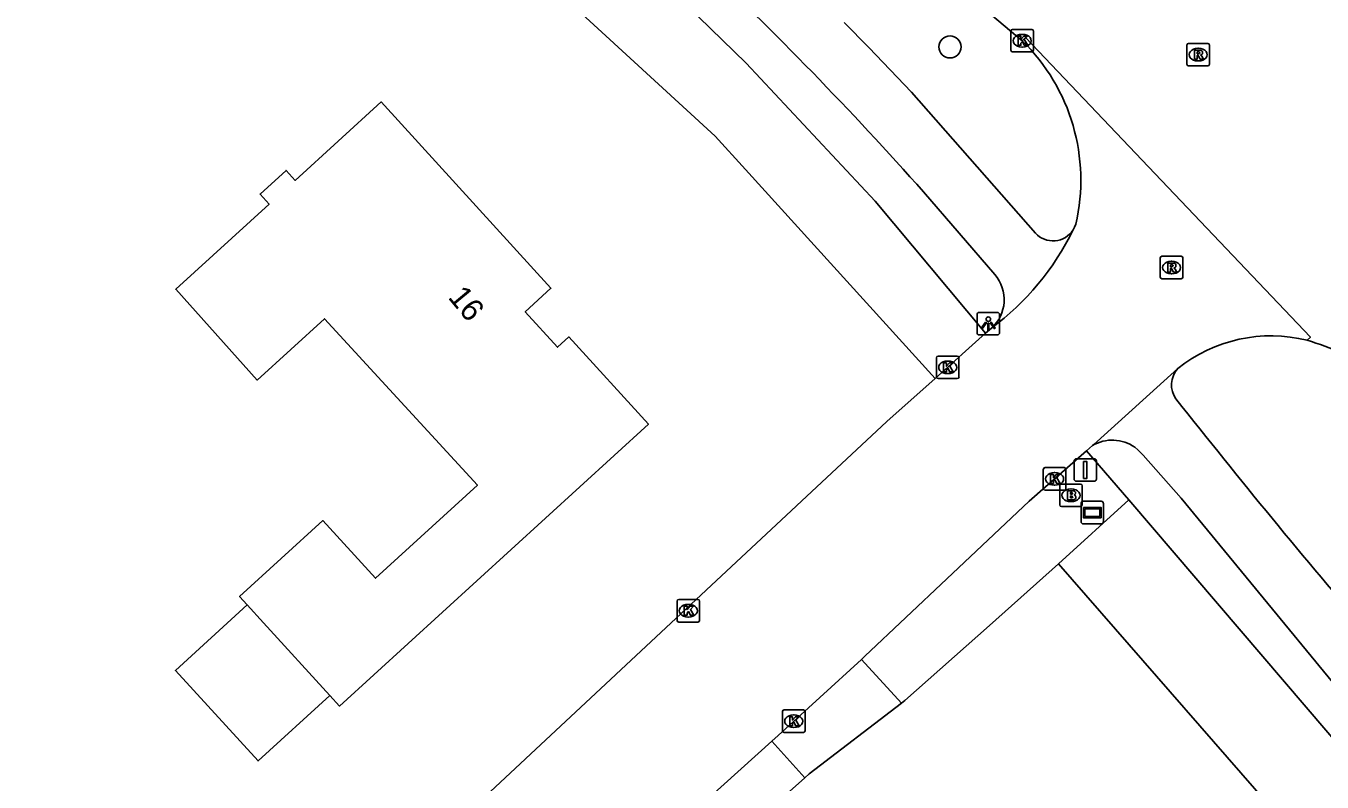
# Model space of a CAD drawing. Extents: x 162417 to 163721, y 384268 to 385416.
# Drawn here: x 163382.6 to 163440.1, y 385193.2 to 385226.8 of the extents above; entities that cross this region are included whole.
import ezdxf

# ---------------------------------------------------------------- set-up
doc = ezdxf.new("R2010")
doc.units = 0
for name, color, linetype in [('IMGEO_Boom', 7, 'Continuous'), ('IMGEO_Brandkraan', 7, 'Continuous'), ('IMGEO_Fietspad_open', 7, 'Continuous'), ('IMGEO_Gemengd_bos', 7, 'Continuous'), ('IMGEO_Groenvoorziening', 7, 'Continuous'), ('IMGEO_Kolk', 7, 'Continuous'), ('IMGEO_Lichtpunt', 7, 'Continuous'), ('IMGEO_Pand', 7, 'Continuous'), ('IMGEO_Pand_nummerreeks', 7, 'Continuous'), ('IMGEO_Rijbaan_lokaal_gesloten', 7, 'Continuous'), ('IMGEO_Rioolput', 7, 'Continuous'), ('IMGEO_Verkeersbordpaal', 7, 'Continuous'), ('IMGEO_Verklikker', 7, 'Continuous'), ('IMGEO_Voetpad_open', 7, 'Continuous')]:
    doc.layers.add(name, color=color, linetype=linetype)

msp = doc.modelspace()

# ---------------------------------------------------------------- linework, layer by layer
at = {"layer": 'IMGEO_Boom'}
msp.add_circle((163423.593, 385225.822), 0.489, dxfattribs=at)
at = {"layer": 'IMGEO_Brandkraan'}
for p, q in [((163428.459, 385205.514), (163428.459, 385206.366)), ((163428.534, 385206.44), (163429.386, 385206.44)), ((163428.947, 385206.22), (163428.972, 385206.22)), ((163429.46, 385206.366), (163429.46, 385205.514)), ((163429.386, 385205.44), (163428.534, 385205.44)), ((163428.97, 385205.66), (163428.945, 385205.66))]:
    msp.add_line(p, q, dxfattribs=at)
for points in [[(163428.459, 385205.514), (163428.459, 385206.366)], [(163428.534, 385206.44), (163429.386, 385206.44)], [(163428.807, 385206.14), (163428.807, 385205.74), (163429.02, 385205.74)], [(163429.038, 385206.14), (163428.807, 385206.14)], [(163428.986, 385206.059), (163428.932, 385206.059), (163428.932, 385205.983)], [(163428.932, 385205.983), (163428.985, 385205.983)], [(163429.46, 385206.366), (163429.46, 385205.514)], [(163429.386, 385205.44), (163428.534, 385205.44)], [(163428.994, 385205.907), (163428.932, 385205.907), (163428.932, 385205.826)], [(163428.932, 385205.826), (163428.994, 385205.826)]]:
    msp.add_lwpolyline(points, dxfattribs=at)
for centre, radius, start, end in [((163428.536, 385206.364), 0.0765, 91.55205, 178.44795), ((163428.536, 385206.364), 0.0765, 91.55205, 178.44795), ((163428.987, 385206.021), 0.0379, 267.82845, 90.93552), ((163429.042, 385205.995), 0.145, 59.4692, 91.53667), ((163429.067, 385206.042), 0.0922, 285.51372, 58.15012), ((163429.072, 385205.85), 0.105, 301.31148, 78.98903), ((163429.384, 385206.364), 0.0765, 1.55205, 88.44795), ((163429.384, 385206.364), 0.0765, 1.55205, 88.44795), ((163428.536, 385205.516), 0.0765, 181.55205, 268.44795), ((163428.536, 385205.516), 0.0765, 181.55205, 268.44795), ((163428.995, 385205.866), 0.0404, 269.87594, 90.50774), ((163429.026, 385205.991), 0.251, 268.66757, 293.53466), ((163429.384, 385205.516), 0.0765, 271.55205, 358.44795), ((163429.384, 385205.516), 0.0765, 271.55205, 358.44795)]:
    msp.add_arc(centre, radius, start, end, dxfattribs=at)
for centre, major_axis, ratio, start_param, end_param in [((163428.946, 385205.94), (-0.387, 0.002), 0.722429, 4.712389, 7.853982), ((163428.971, 385205.94), (-0.39, 0.002), 0.717154, 1.570796, 4.712389)]:
    msp.add_ellipse(centre, major_axis=major_axis, ratio=ratio, start_param=start_param, end_param=end_param, dxfattribs=at)
at = {"layer": 'IMGEO_Fietspad_open'}
for points in [[(163427.379, 385217.563), (163421.89, 385223.809), (163419.988, 385225.795), (163418.903, 385226.906)], [(163422.42, 385219.391), (163425.582, 385215.726)], [(163431.787, 385208.07), (163431.922, 385207.954), (163432.159, 385207.714), (163433.841, 385205.808), (163444.2, 385193.223), (163470.237, 385163.265), (163478.767, 385152.569), (163484.279, 385144.583), (163488.178, 385138.38), (163494.183, 385128.236), (163502.766, 385111.711), (163507.809, 385101.794), (163517.384, 385082.877), (163528.502, 385060.963)]]:
    msp.add_lwpolyline(points, dxfattribs=at)
for centre, radius, start, end in [((163299.088, 385109.656), 165.084, 41.6612, 46.68774), ((163428.16, 385218.28), 1.06, 222.5679, 327.40112), ((163424.297, 385214.615), 1.698, 311.7937, 40.84056), ((163434.498, 385210.835), 1.084, 137.77915, 214.9254), ((163733.724, 385447.945), 382.864, 218.38399, 220.41896), ((163430.791, 385206.657), 1.729, 54.82845, 120.65616)]:
    msp.add_arc(centre, radius, start, end, dxfattribs=at)
at = {"layer": 'IMGEO_Gemengd_bos'}
for points in [[(163431.516, 385205.744), (163428.403, 385202.907)], [(163309.738, 385096.794), (163334.35, 385105.91), (163401.172, 385130.32), (163403.611, 385131.145), (163408.387, 385133.189), (163412.924, 385135.721), (163417.172, 385138.714), (163421.083, 385142.134), (163454.583, 385172.899), (163428.403, 385202.907)]]:
    msp.add_lwpolyline(points, dxfattribs=at)
at = {"layer": 'IMGEO_Groenvoorziening'}
for points in [[(163397.756, 385235.453), (163401.687, 385232.409), (163413.183, 385221.864), (163414.526, 385220.382), (163422.928, 385211.112)], [(163428.403, 385202.907), (163425.337, 385200.174), (163421.592, 385196.836), (163421.439, 385196.719)], [(163417.147, 385193.417), (163401.29, 385179.305), (163399.075, 385177.547)]]:
    msp.add_lwpolyline(points, dxfattribs=at)
at = {"layer": 'IMGEO_Kolk'}
for p, q in [((163426.293, 385225.67), (163426.293, 385226.522)), ((163426.368, 385226.596), (163427.22, 385226.596)), ((163426.781, 385226.376), (163426.806, 385226.376)), ((163427.294, 385226.522), (163427.294, 385225.67)), ((163427.22, 385225.596), (163426.368, 385225.596)), ((163426.804, 385225.816), (163426.779, 385225.816)), ((163422.99, 385211.187), (163422.99, 385212.039)), ((163423.065, 385212.113), (163423.917, 385212.113)), ((163423.478, 385211.893), (163423.503, 385211.893)), ((163423.991, 385212.039), (163423.991, 385211.187)), ((163423.917, 385211.113), (163423.065, 385211.113)), ((163423.501, 385211.333), (163423.476, 385211.333)), ((163427.731, 385206.241), (163427.731, 385207.093)), ((163427.806, 385207.167), (163428.658, 385207.167)), ((163428.732, 385207.093), (163428.732, 385206.241)), ((163428.219, 385206.947), (163428.244, 385206.947)), ((163428.658, 385206.167), (163427.806, 385206.167)), ((163428.242, 385206.387), (163428.217, 385206.387)), ((163411.485, 385200.395), (163411.485, 385201.247)), ((163411.56, 385201.321), (163412.412, 385201.321)), ((163411.973, 385201.101), (163411.998, 385201.101)), ((163412.486, 385201.247), (163412.486, 385200.395)), ((163412.412, 385200.321), (163411.56, 385200.321)), ((163411.996, 385200.541), (163411.971, 385200.541)), ((163416.161, 385195.497), (163416.161, 385196.349)), ((163416.236, 385196.423), (163417.088, 385196.423)), ((163416.649, 385196.203), (163416.674, 385196.203)), ((163417.162, 385196.349), (163417.162, 385195.497)), ((163416.672, 385195.643), (163416.647, 385195.643)), ((163417.088, 385195.423), (163416.236, 385195.423))]:
    msp.add_line(p, q, dxfattribs=at)
for points in [[(163426.293, 385225.67), (163426.293, 385226.522)], [(163426.368, 385226.596), (163427.22, 385226.596)], [(163426.614, 385226.296), (163426.737, 385226.296), (163426.737, 385226.145), (163426.867, 385226.296), (163427.031, 385226.296), (163426.885, 385226.145), (163427.038, 385225.896), (163426.886, 385225.896), (163426.801, 385226.06), (163426.737, 385225.993), (163426.737, 385225.896), (163426.614, 385225.896), (163426.614, 385226.296)], [(163427.294, 385226.522), (163427.294, 385225.67)], [(163427.22, 385225.596), (163426.368, 385225.596)], [(163422.99, 385211.187), (163422.99, 385212.039)], [(163423.065, 385212.113), (163423.917, 385212.113)], [(163423.311, 385211.813), (163423.434, 385211.813), (163423.434, 385211.662), (163423.564, 385211.813), (163423.728, 385211.813), (163423.582, 385211.662), (163423.735, 385211.413), (163423.583, 385211.413), (163423.498, 385211.577), (163423.434, 385211.51), (163423.434, 385211.413), (163423.311, 385211.413), (163423.311, 385211.813)], [(163423.991, 385212.039), (163423.991, 385211.187)], [(163423.917, 385211.113), (163423.065, 385211.113)], [(163427.731, 385206.241), (163427.731, 385207.093)], [(163427.806, 385207.167), (163428.658, 385207.167)], [(163428.732, 385207.093), (163428.732, 385206.241)], [(163428.052, 385206.867), (163428.175, 385206.867), (163428.175, 385206.716), (163428.305, 385206.867), (163428.469, 385206.867), (163428.323, 385206.716), (163428.476, 385206.467), (163428.324, 385206.467), (163428.239, 385206.631), (163428.175, 385206.564), (163428.175, 385206.467), (163428.052, 385206.467), (163428.052, 385206.867)], [(163428.658, 385206.167), (163427.806, 385206.167)], [(163411.485, 385200.395), (163411.485, 385201.247)], [(163411.56, 385201.321), (163412.412, 385201.321)], [(163411.806, 385201.021), (163411.929, 385201.021), (163411.929, 385200.87), (163412.059, 385201.021), (163412.223, 385201.021), (163412.077, 385200.87), (163412.23, 385200.621), (163412.078, 385200.621), (163411.993, 385200.785), (163411.929, 385200.718), (163411.929, 385200.621), (163411.806, 385200.621), (163411.806, 385201.021)], [(163412.486, 385201.247), (163412.486, 385200.395)], [(163412.412, 385200.321), (163411.56, 385200.321)], [(163416.161, 385195.497), (163416.161, 385196.349)], [(163416.236, 385196.423), (163417.088, 385196.423)], [(163417.162, 385196.349), (163417.162, 385195.497)], [(163416.482, 385196.123), (163416.605, 385196.123), (163416.605, 385195.972), (163416.735, 385196.123), (163416.899, 385196.123), (163416.753, 385195.972), (163416.906, 385195.723), (163416.754, 385195.723), (163416.669, 385195.887), (163416.605, 385195.82), (163416.605, 385195.723), (163416.482, 385195.723), (163416.482, 385196.123)], [(163417.088, 385195.423), (163416.236, 385195.423)]]:
    msp.add_lwpolyline(points, dxfattribs=at)
for centre, start, end in [((163426.37, 385226.52), 91.55205, 178.44795), ((163426.37, 385226.52), 91.55205, 178.44795), ((163427.218, 385226.52), 1.55205, 88.44795), ((163427.218, 385226.52), 1.55205, 88.44795), ((163426.37, 385225.672), 181.55205, 268.44795), ((163426.37, 385225.672), 181.55205, 268.44795), ((163427.218, 385225.672), 271.55205, 358.44795), ((163427.218, 385225.672), 271.55205, 358.44795), ((163423.067, 385212.037), 91.55205, 178.44795), ((163423.067, 385212.037), 91.55205, 178.44795), ((163423.915, 385212.037), 1.55205, 88.44795), ((163423.915, 385212.037), 1.55205, 88.44795), ((163423.067, 385211.189), 181.55205, 268.44795), ((163423.067, 385211.189), 181.55205, 268.44795), ((163423.915, 385211.189), 271.55205, 358.44795), ((163423.915, 385211.189), 271.55205, 358.44795), ((163427.808, 385207.091), 91.55205, 178.44795), ((163427.808, 385207.091), 91.55205, 178.44795), ((163428.656, 385207.091), 1.55205, 88.44795), ((163428.656, 385207.091), 1.55205, 88.44795), ((163427.808, 385206.243), 181.55205, 268.44795), ((163427.808, 385206.243), 181.55205, 268.44795), ((163428.656, 385206.243), 271.55205, 358.44795), ((163428.656, 385206.243), 271.55205, 358.44795), ((163411.562, 385201.245), 91.55205, 178.44795), ((163411.562, 385201.245), 91.55205, 178.44795), ((163412.41, 385201.245), 1.55205, 88.44795), ((163412.41, 385201.245), 1.55205, 88.44795), ((163411.562, 385200.397), 181.55205, 268.44795), ((163411.562, 385200.397), 181.55205, 268.44795), ((163412.41, 385200.397), 271.55205, 358.44795), ((163412.41, 385200.397), 271.55205, 358.44795), ((163416.238, 385196.347), 91.55205, 178.44795), ((163416.238, 385196.347), 91.55205, 178.44795), ((163417.086, 385196.347), 1.55205, 88.44795), ((163417.086, 385196.347), 1.55205, 88.44795), ((163416.238, 385195.499), 181.55205, 268.44795), ((163416.238, 385195.499), 181.55205, 268.44795), ((163417.086, 385195.499), 271.55205, 358.44795), ((163417.086, 385195.499), 271.55205, 358.44795)]:
    msp.add_arc(centre, 0.0765, start, end, dxfattribs=at)
for centre, major_axis, ratio, start_param, end_param in [((163426.78, 385226.096), (-0.387, 0.002), 0.722429, 4.712389, 7.853982), ((163426.805, 385226.096), (-0.39, 0.002), 0.717154, 1.570796, 4.712389), ((163423.477, 385211.613), (-0.387, 0.002), 0.722429, 4.712389, 7.853982), ((163423.502, 385211.613), (-0.39, 0.002), 0.717154, 1.570796, 4.712389), ((163428.218, 385206.667), (-0.387, 0.002), 0.722429, 4.712389, 7.853982), ((163428.243, 385206.667), (-0.39, 0.002), 0.717154, 1.570796, 4.712389), ((163411.972, 385200.821), (-0.387, 0.002), 0.722429, 4.712389, 7.853982), ((163411.997, 385200.821), (-0.39, 0.002), 0.717154, 1.570796, 4.712389), ((163416.648, 385195.923), (-0.387, 0.002), 0.722429, 4.712389, 7.853982), ((163416.673, 385195.923), (-0.39, 0.002), 0.717154, 1.570796, 4.712389)]:
    msp.add_ellipse(centre, major_axis=major_axis, ratio=ratio, start_param=start_param, end_param=end_param, dxfattribs=at)
at = {"layer": 'IMGEO_Lichtpunt'}
for p, q in [((163425.693, 385214.049), (163424.885, 385214.049)), ((163425.693, 385214.049), (163424.885, 385214.049)), ((163424.791, 385213.954), (163424.791, 385213.147)), ((163424.791, 385213.954), (163424.791, 385213.147)), ((163425.787, 385213.147), (163425.787, 385213.954)), ((163425.787, 385213.147), (163425.787, 385213.954)), ((163424.885, 385213.053), (163425.693, 385213.053)), ((163424.885, 385213.053), (163425.693, 385213.053))]:
    msp.add_line(p, q, dxfattribs=at)
for points in [[(163425.165, 385213.618), (163425.204, 385213.59), (163425.016, 385213.328), (163424.978, 385213.355), (163425.165, 385213.618)], [(163425.267, 385213.57), (163425.314, 385213.57), (163425.314, 385213.248), (163425.267, 385213.248), (163425.267, 385213.57)], [(163425.377, 385213.59), (163425.415, 385213.617), (163425.602, 385213.355), (163425.563, 385213.327), (163425.377, 385213.59)]]:
    msp.add_lwpolyline(points, dxfattribs=at)
msp.add_circle((163425.29, 385213.752), 0.0994, dxfattribs=at)
for centre, start, end in [((163424.885, 385213.954), 90, 180), ((163424.885, 385213.954), 90, 180), ((163425.693, 385213.954), 0, 90), ((163425.693, 385213.954), 0, 90), ((163424.885, 385213.147), 180, 270), ((163424.885, 385213.147), 180, 270), ((163425.693, 385213.147), 270, 0), ((163425.693, 385213.147), 270, 360)]:
    msp.add_arc(centre, 0.0946, start, end, dxfattribs=at)
at = {"layer": 'IMGEO_Pand'}
for points in [[(163396.087, 385197.066), (163396.516, 385196.596), (163410.218, 385209.096), (163406.69, 385212.964), (163406.188, 385212.506), (163404.754, 385214.078), (163405.896, 385215.12), (163398.36, 385223.379), (163394.548, 385219.902), (163394.145, 385220.346), (163392.992, 385219.297), (163393.397, 385218.854), (163389.252, 385215.074), (163392.871, 385211.048), (163395.852, 385213.768), (163402.635, 385206.393), (163398.11, 385202.265), (163395.781, 385204.819), (163392.088, 385201.45), (163392.426, 385201.079)], [(163392.426, 385201.079), (163389.243, 385198.175), (163392.904, 385194.162), (163396.087, 385197.066)], [(163396.087, 385197.066), (163393.147, 385200.29), (163392.426, 385201.079)]]:
    msp.add_lwpolyline(points, dxfattribs=at)
at = {"layer": 'IMGEO_Rijbaan_lokaal_gesloten'}
for points in [[(163423.595, 385228.801), (163426.798, 385226.095)], [(163426.798, 385226.095), (163426.943, 385226.233), (163439.577, 385212.956), (163439.432, 385212.818)], [(163429.053, 385217.709), (163429.117, 385217.832), (163429.17, 385217.958)], [(163422.928, 385211.112), (163425.17, 385213.131)], [(163425.17, 385213.131), (163425.429, 385213.349)], [(163394.726, 385185.434), (163400.757, 385190.511), (163420.795, 385209.205), (163422.928, 385211.112)], [(163433.695, 385211.563), (163430.116, 385208.329), (163429.964, 385208.192), (163429.91, 385208.144)], [(163429.648, 385207.914), (163427.108, 385205.674), (163423.458, 385202.232), (163419.819, 385198.801), (163419.667, 385198.662)], [(163429.91, 385208.144), (163429.648, 385207.914)], [(163419.667, 385198.662), (163415.974, 385195.293), (163415.688, 385195.035)], [(163415.688, 385195.035), (163402.705, 385183.33), (163398.036, 385179.474)]]:
    msp.add_lwpolyline(points, dxfattribs=at)
for centre, radius, start, end in [((163420.738, 385219.914), 8.656, 346.93805, 45.56559), ((163418.291, 385222.968), 11.978, 306.57759, 333.95619), ((163437.843, 385206.341), 6.669, 76.21663, 128.46214), ((163434.996, 385198.578), 14.915, 60.05669, 72.69854)]:
    msp.add_arc(centre, radius, start, end, dxfattribs=at)
at = {"layer": 'IMGEO_Rioolput'}
for p, q in [((163434.099, 385225.053), (163434.099, 385225.905)), ((163434.174, 385225.979), (163435.026, 385225.979)), ((163434.587, 385225.759), (163434.612, 385225.759)), ((163435.1, 385225.905), (163435.1, 385225.053)), ((163435.026, 385224.979), (163434.174, 385224.979)), ((163434.61, 385225.199), (163434.585, 385225.199)), ((163432.917, 385215.613), (163432.917, 385216.465)), ((163432.992, 385216.539), (163433.844, 385216.539)), ((163433.405, 385216.319), (163433.43, 385216.319)), ((163433.918, 385216.465), (163433.918, 385215.613)), ((163433.428, 385215.759), (163433.403, 385215.759)), ((163433.844, 385215.539), (163432.992, 385215.539))]:
    msp.add_line(p, q, dxfattribs=at)
for points in [[(163434.099, 385225.053), (163434.099, 385225.905)], [(163434.174, 385225.979), (163435.026, 385225.979)], [(163434.688, 385225.677), (163434.436, 385225.679), (163434.436, 385225.279)], [(163434.614, 385225.598), (163434.56, 385225.598), (163434.56, 385225.517)], [(163434.56, 385225.517), (163434.612, 385225.517)], [(163435.1, 385225.905), (163435.1, 385225.053)], [(163435.026, 385224.979), (163434.174, 385224.979)], [(163434.436, 385225.279), (163434.56, 385225.279), (163434.56, 385225.441), (163434.571, 385225.441)], [(163434.618, 385225.412), (163434.689, 385225.279), (163434.829, 385225.279), (163434.764, 385225.405)], [(163432.917, 385215.613), (163432.917, 385216.465)], [(163432.992, 385216.539), (163433.844, 385216.539)], [(163433.918, 385216.465), (163433.918, 385215.613)], [(163433.506, 385216.237), (163433.254, 385216.239), (163433.254, 385215.839)], [(163433.254, 385215.839), (163433.378, 385215.839), (163433.378, 385216.001), (163433.389, 385216.001)], [(163433.432, 385216.158), (163433.378, 385216.158), (163433.378, 385216.077)], [(163433.378, 385216.077), (163433.43, 385216.077)], [(163433.436, 385215.972), (163433.507, 385215.839), (163433.647, 385215.839), (163433.582, 385215.965)], [(163433.844, 385215.539), (163432.992, 385215.539)]]:
    msp.add_lwpolyline(points, dxfattribs=at)
for centre, radius, start, end in [((163434.176, 385225.903), 0.0765, 91.55205, 178.44795), ((163434.176, 385225.903), 0.0765, 91.55205, 178.44795), ((163434.596, 385225.706), 0.19, 274.7715, 282.96867), ((163434.62, 385225.502), 0.0964, 77.00612, 93.18647), ((163434.634, 385225.559), 0.0378, 276.66336, 79.67722), ((163434.687, 385225.567), 0.109, 350.36119, 89.41601), ((163434.685, 385225.567), 0.112, 277.58423, 350.98172), ((163435.024, 385225.903), 0.0765, 1.55205, 88.44795), ((163435.024, 385225.903), 0.0765, 1.55205, 88.44795), ((163434.176, 385225.055), 0.0765, 181.55205, 268.44795), ((163434.176, 385225.055), 0.0765, 181.55205, 268.44795), ((163434.57, 385225.388), 0.0533, 26.02933, 88.69889), ((163434.669, 385225.352), 0.108, 29.51342, 73.79051), ((163435.024, 385225.055), 0.0765, 271.55205, 358.44795), ((163435.024, 385225.055), 0.0765, 271.55205, 358.44795), ((163432.994, 385216.463), 0.0765, 91.55205, 178.44795), ((163432.994, 385216.463), 0.0765, 91.55205, 178.44795), ((163433.842, 385216.463), 0.0765, 1.55205, 88.44795), ((163433.842, 385216.463), 0.0765, 1.55205, 88.44795), ((163433.388, 385215.948), 0.0533, 26.02933, 88.69889), ((163433.414, 385216.266), 0.19, 274.7715, 282.96867), ((163433.438, 385216.062), 0.0964, 77.00612, 93.18647), ((163433.452, 385216.119), 0.0378, 276.66336, 79.67722), ((163433.505, 385216.127), 0.109, 350.36119, 89.41601), ((163433.503, 385216.127), 0.112, 277.58423, 350.98172), ((163433.487, 385215.912), 0.108, 29.51342, 73.79051), ((163432.994, 385215.615), 0.0765, 181.55205, 268.44795), ((163432.994, 385215.615), 0.0765, 181.55205, 268.44795), ((163433.842, 385215.615), 0.0765, 271.55205, 358.44795), ((163433.842, 385215.615), 0.0765, 271.55205, 358.44795)]:
    msp.add_arc(centre, radius, start, end, dxfattribs=at)
for centre, major_axis, ratio, start_param, end_param in [((163434.586, 385225.479), (-0.387, 0.002), 0.722429, 4.712389, 7.853982), ((163434.611, 385225.479), (-0.39, 0.002), 0.717154, 1.570796, 4.712389), ((163433.404, 385216.039), (-0.387, 0.002), 0.722429, 4.712389, 7.853982), ((163433.429, 385216.039), (-0.39, 0.002), 0.717154, 1.570796, 4.712389)]:
    msp.add_ellipse(centre, major_axis=major_axis, ratio=ratio, start_param=start_param, end_param=end_param, dxfattribs=at)
at = {"layer": 'IMGEO_Verkeersbordpaal'}
for p, q in [((163429.097, 385206.662), (163429.097, 385207.462)), ((163429.097, 385207.462), (163429.097, 385206.662)), ((163429.197, 385207.562), (163429.987, 385207.562)), ((163429.987, 385207.562), (163429.197, 385207.562)), ((163430.087, 385207.462), (163430.087, 385206.662)), ((163430.087, 385206.662), (163430.087, 385207.462)), ((163429.987, 385206.562), (163429.197, 385206.562)), ((163429.197, 385206.562), (163429.987, 385206.562))]:
    msp.add_line(p, q, dxfattribs=at)
msp.add_lwpolyline([(163429.517, 385207.437), (163429.667, 385207.437), (163429.667, 385206.687), (163429.517, 385206.687), (163429.517, 385207.437)], dxfattribs=at)
for centre, start, end in [((163429.197, 385207.462), 90, 180), ((163429.197, 385207.462), 90, 180), ((163429.987, 385207.462), 0, 90), ((163429.987, 385207.462), 360, 90), ((163429.197, 385206.662), 180, 270), ((163429.197, 385206.662), 180, 270), ((163429.987, 385206.662), 270, 0), ((163429.987, 385206.662), 270, 0)]:
    msp.add_arc(centre, 0.1, start, end, dxfattribs=at)
at = {"layer": 'IMGEO_Verklikker'}
for p, q in [((163429.407, 385204.773), (163429.407, 385205.573)), ((163429.407, 385205.573), (163429.407, 385204.773)), ((163429.507, 385205.673), (163430.297, 385205.673)), ((163430.297, 385205.673), (163429.507, 385205.673)), ((163430.397, 385205.573), (163430.397, 385204.773)), ((163430.397, 385204.773), (163430.397, 385205.573)), ((163430.297, 385204.673), (163429.507, 385204.673)), ((163429.507, 385204.673), (163430.297, 385204.673))]:
    msp.add_line(p, q, dxfattribs=at)
for points in [[(163429.508, 385205.405), (163430.296, 385205.405), (163430.296, 385204.941), (163429.508, 385204.941), (163429.508, 385205.405)], [(163429.573, 385205.34), (163429.573, 385205.006), (163430.231, 385205.006), (163430.231, 385205.34), (163429.573, 385205.34)]]:
    msp.add_lwpolyline(points, dxfattribs=at)
for centre, start, end in [((163429.507, 385205.573), 90, 180), ((163429.507, 385205.573), 90, 180), ((163430.297, 385205.573), 0, 90), ((163430.297, 385205.573), 360, 90), ((163429.507, 385204.773), 180, 270), ((163429.507, 385204.773), 180, 270), ((163430.297, 385204.773), 270, 0), ((163430.297, 385204.773), 270, 0)]:
    msp.add_arc(centre, 0.1, start, end, dxfattribs=at)
at = {"layer": 'IMGEO_Voetpad_open'}
for points in [[(163425.17, 385213.131), (163420.278, 385218.981), (163414.552, 385225.097), (163407.672, 385231.793), (163404.493, 385234.62), (163402.506, 385236.206)], [(163431.516, 385205.744), (163429.648, 385207.914)], [(163469.791, 385161.005), (163431.516, 385205.744)], [(163419.667, 385198.662), (163421.439, 385196.719)], [(163421.439, 385196.719), (163417.349, 385193.597), (163417.147, 385193.417)], [(163417.147, 385193.417), (163415.688, 385195.035)]]:
    msp.add_lwpolyline(points, dxfattribs=at)

# ---------------------------------------------------------------- texts
at = {"layer": 'IMGEO_Pand_nummerreeks'}
msp.add_text('16', height=1, rotation=309.70004, dxfattribs=at).set_placement((163401.296, 385214.708))

doc.saveas('drawing.dxf')
